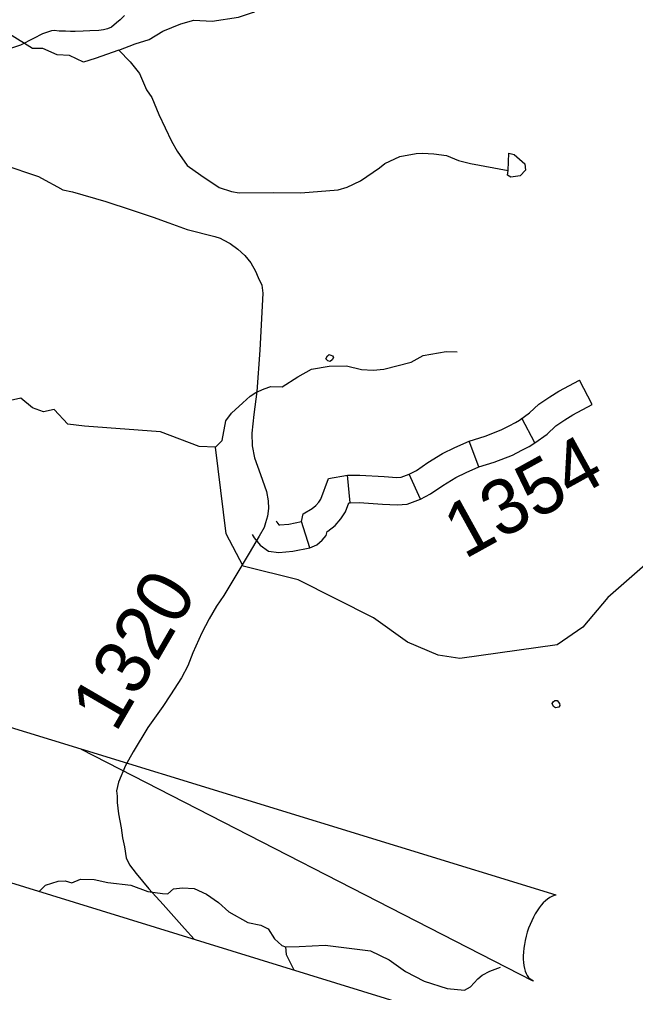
# Model space of a CAD drawing. Extents: x 1347947 to 1350662, y 1027710 to 1030532.
# Drawn here: x 1348191.6 to 1348242, y 1028722.6 to 1028802.3 of the extents above; entities that cross this region are included whole.
import ezdxf

# ---------------------------------------------------------------- set-up
doc = ezdxf.new("R2010")
doc.units = 0
for name, color, linetype in [('Default', 7, 'Continuous'), ('Prop Leader Line Light', 7, 'Continuous'), ('Prop North Arrow for Plan Sheets CELL', 7, 'Continuous'), ('Prop WCC CELL', 7, 'Continuous')]:
    doc.layers.add(name, color=color, linetype=linetype)

msp = doc.modelspace()

# ---------------------------------------------------------------- linework, layer by layer
at = {"layer": 'Default'}
for p, q in [((1348199.71, 1028799.768), (1348200.64, 1028798.811)), ((1348238.502, 1028770.744), (1348237.451, 1028772.733)), ((1348233.802, 1028767.597), (1348232.741, 1028769.606)), ((1348229.202, 1028765.617), (1348228.419, 1028767.73)), ((1348224.426, 1028762.973), (1348223.513, 1028765.035)), ((1348218.68, 1028762.687), (1348218.457, 1028764.932)), ((1348215.372, 1028759.001), (1348214.675, 1028761.153))]:
    msp.add_line(p, q, dxfattribs=at)
for points in [[(1348199.71, 1028799.768), (1348201.069, 1028800.27), (1348202.213, 1028800.625), (1348203.313, 1028801.32), (1348204.79, 1028801.926), (1348205.865, 1028802.202), (1348207.367, 1028802.124), (1348209.527, 1028802.47), (1348210.745, 1028802.859), (1348212.365, 1028803.82), (1348216.434, 1028804.782), (1348217.633, 1028805.178), (1348219.233, 1028805.496), (1348221.756, 1028806.061), (1348222.096, 1028805.983), (1348222.959, 1028806.7), (1348224.117, 1028807.212), (1348225.207, 1028807.3), (1348227.046, 1028807.308)], [(1348200.195, 1028802.591), (1348199.82, 1028802.247), (1348199.539, 1028801.998), (1348199.118, 1028801.646), (1348198.794, 1028801.507), (1348198.476, 1028801.412), (1348198.072, 1028801.364), (1348197.346, 1028801.352), (1348196.79, 1028801.3), (1348196.159, 1028801.273), (1348195.752, 1028801.298), (1348195.36, 1028801.318), (1348194.841, 1028801.304), (1348194.427, 1028801.356), (1348194.204, 1028801.332), (1348193.468, 1028801.087), (1348192.72, 1028800.725), (1348191.656, 1028800.159), (1348190.927, 1028799.907), (1348189.94, 1028799.78), (1348188.78, 1028799.71), (1348187.697, 1028799.672), (1348186.821, 1028799.833)], [(1348199.71, 1028799.768), (1348197.785, 1028799.07), (1348196.825, 1028798.777), (1348195.689, 1028799.329), (1348194.672, 1028799.377), (1348193.487, 1028799.904), (1348192.653, 1028799.892), (1348190.781, 1028801.069)], [(1348200.64, 1028798.811), (1348201.422, 1028797.841), (1348201.988, 1028796.496), (1348202.421, 1028795.87), (1348202.994, 1028794.482), (1348204.04, 1028792.295), (1348204.508, 1028791.479), (1348205.323, 1028790.315), (1348206.43, 1028789.517), (1348207.953, 1028788.512), (1348208.96, 1028788.179), (1348209.59, 1028788.059), (1348212.354, 1028788.088), (1348214.63, 1028788.062), (1348217.697, 1028788.311), (1348218.424, 1028788.526), (1348219.504, 1028789.043), (1348221.071, 1028790.129), (1348221.498, 1028790.471), (1348222.742, 1028791.053)], [(1348183.751, 1028792.494), (1348187.272, 1028791.256), (1348190.213, 1028790.399), (1348193.156, 1028789.399), (1348193.699, 1028789.106), (1348194.712, 1028788.569), (1348195.143, 1028788.322), (1348195.92, 1028788.154), (1348198.65, 1028787.357), (1348200.732, 1028786.675), (1348202.535, 1028786.072), (1348203.816, 1028785.622), (1348205.314, 1028785.076), (1348207.576, 1028784.481), (1348208.014, 1028784.346), (1348208.259, 1028784.233), (1348208.846, 1028783.917), (1348209.48, 1028783.453), (1348210.049, 1028782.928)], [(1348222.742, 1028791.053), (1348224.072, 1028791.3), (1348224.591, 1028791.323), (1348225.533, 1028791.278), (1348226.559, 1028791.122), (1348227.54, 1028790.719), (1348228.534, 1028790.473), (1348231.6, 1028789.908)], [(1348231.6, 1028789.908), (1348231.664, 1028791.315), (1348232.094, 1028791.205), (1348232.971, 1028790.448), (1348233.031, 1028789.918), (1348232.604, 1028789.456), (1348231.817, 1028789.364), (1348231.564, 1028789.514), (1348231.6, 1028789.908)], [(1348231.6, 1028789.908), (1348231.664, 1028791.315), (1348232.094, 1028791.205), (1348232.971, 1028790.448), (1348233.031, 1028789.918), (1348232.604, 1028789.456), (1348231.817, 1028789.364), (1348231.564, 1028789.514), (1348231.6, 1028789.908)], [(1348210.049, 1028782.928), (1348210.524, 1028782.344), (1348210.916, 1028781.667), (1348211.145, 1028781.145), (1348211.441, 1028780.501), (1348211.513, 1028779.855), (1348211.266, 1028775.173), (1348211.018, 1028771.81), (1348210.777, 1028769.923), (1348210.62, 1028768.397), (1348210.643, 1028767.344), (1348210.834, 1028766.378), (1348211.325, 1028765.007), (1348211.829, 1028763.598), (1348211.964, 1028762.84), (1348211.993, 1028762.217), (1348211.901, 1028761.575), (1348211.732, 1028761.033), (1348211.623, 1028760.645)], [(1348207.638, 1028767.241), (1348208.176, 1028767.787), (1348208.476, 1028769.395), (1348208.961, 1028770.02), (1348209.87, 1028770.863), (1348210.476, 1028771.426), (1348210.943, 1028771.71), (1348211.624, 1028772.022), (1348212.175, 1028772.196), (1348213.088, 1028772.182), (1348214.391, 1028772.988), (1348215.491, 1028773.621), (1348216.95, 1028773.884), (1348218.381, 1028773.891), (1348219.605, 1028773.603), (1348220.56, 1028773.533), (1348221.415, 1028773.64), (1348223.652, 1028774.201), (1348224.64, 1028774.75), (1348226.545, 1028775.061), (1348227.422, 1028775.058)], [(1348216.835, 1028774.312), (1348216.668, 1028774.473), (1348216.818, 1028774.725), (1348216.954, 1028774.822), (1348217.219, 1028774.707), (1348217.314, 1028774.572), (1348217.208, 1028774.385), (1348217.041, 1028774.259), (1348216.835, 1028774.312)], [(1348212.601, 1028761.201), (1348212.66, 1028761.098), (1348212.838, 1028760.882), (1348212.904, 1028760.873), (1348213.654, 1028760.937), (1348214.675, 1028761.153), (1348214.825, 1028761.778), (1348215.566, 1028762.222), (1348215.869, 1028762.46), (1348216.104, 1028762.736), (1348216.268, 1028762.981), (1348216.895, 1028764.659), (1348218.457, 1028764.932), (1348219.449, 1028764.957), (1348221.45, 1028764.825), (1348222.503, 1028764.76), (1348222.838, 1028764.789), (1348223.513, 1028765.035), (1348224.093, 1028765.339), (1348225.039, 1028765.972), (1348226.23, 1028766.723), (1348227.229, 1028767.218), (1348228.419, 1028767.73), (1348229.722, 1028768.139), (1348231.048, 1028768.655), (1348231.703, 1028768.981), (1348232.206, 1028769.251), (1348232.543, 1028769.463), (1348233.355, 1028770.051), (1348234.108, 1028770.762), (1348235.021, 1028771.353), (1348235.749, 1028771.835), (1348237.451, 1028772.733)], [(1348246.557, 1028760.877), (1348239.774, 1028754.932), (1348237.726, 1028752.503), (1348235.611, 1028751.037), (1348227.638, 1028749.93), (1348225.865, 1028750.214), (1348223.355, 1028751.262), (1348220.573, 1028753.261), (1348214.415, 1028756.381), (1348209.916, 1028757.493), (1348208.52, 1028760.13), (1348207.638, 1028767.241), (1348206.299, 1028767.295), (1348203.138, 1028768.487), (1348196.922, 1028768.972), (1348195.535, 1028769.12), (1348194.423, 1028770.322), (1348193.548, 1028770.122), (1348192.645, 1028770.456), (1348191.689, 1028771.253), (1348189.497, 1028770.751)], [(1348210.645, 1028760.089), (1348210.802, 1028759.813), (1348211.306, 1028759.205), (1348211.989, 1028758.732), (1348212.839, 1028758.609), (1348213.984, 1028758.707), (1348215.372, 1028759.001), (1348215.944, 1028759.235), (1348216.388, 1028759.607), (1348216.714, 1028760.006), (1348216.793, 1028760.333), (1348216.846, 1028760.365), (1348217.437, 1028760.831), (1348217.9, 1028761.374), (1348218.284, 1028761.946), (1348218.552, 1028762.665), (1348218.68, 1028762.687), (1348219.403, 1028762.705), (1348221.307, 1028762.58), (1348222.53, 1028762.504), (1348223.327, 1028762.573), (1348224.426, 1028762.973), (1348225.245, 1028763.403), (1348226.264, 1028764.085), (1348227.332, 1028764.759), (1348228.173, 1028765.175), (1348229.202, 1028765.617), (1348230.468, 1028766.015), (1348231.958, 1028766.595), (1348232.737, 1028766.982), (1348233.339, 1028767.306), (1348233.803, 1028767.598), (1348234.794, 1028768.315), (1348235.503, 1028768.986), (1348236.252, 1028769.47), (1348236.897, 1028769.897), (1348238.502, 1028770.744)], [(1348211.623, 1028760.645), (1348211.226, 1028759.961), (1348210.39, 1028758.566), (1348209.314, 1028756.731), (1348208.311, 1028755.086), (1348207.718, 1028754.208), (1348207.129, 1028753.189), (1348206.529, 1028752.032), (1348205.781, 1028750.379), (1348205.375, 1028749.329), (1348204.848, 1028748.348), (1348203.942, 1028746.942), (1348203.337, 1028745.991), (1348202.109, 1028744.279), (1348200.902, 1028742.275), (1348200.255, 1028741.167), (1348199.701, 1028739.81), (1348199.528, 1028739.083), (1348199.592, 1028738.65), (1348199.582, 1028738.127), (1348199.702, 1028737.204), (1348199.919, 1028736.063), (1348200.017, 1028735.243), (1348200.174, 1028734.497), (1348200.334, 1028733.608), (1348200.592, 1028733.031), (1348201.143, 1028732.304), (1348202.182, 1028731.062), (1348203.366, 1028729.78), (1348205.094, 1028727.824), (1348205.895, 1028726.936)], [(1348235.487, 1028745.883), (1348235.318, 1028745.984), (1348235.225, 1028746.241), (1348235.294, 1028746.38), (1348235.436, 1028746.493), (1348235.636, 1028746.483), (1348235.815, 1028746.238), (1348235.843, 1028746.085), (1348235.75, 1028745.935), (1348235.487, 1028745.883)], [(1348235.487, 1028745.883), (1348235.318, 1028745.984), (1348235.225, 1028746.241), (1348235.294, 1028746.38), (1348235.436, 1028746.493), (1348235.636, 1028746.483), (1348235.815, 1028746.238), (1348235.843, 1028746.085), (1348235.75, 1028745.935), (1348235.487, 1028745.883)], [(1348193.201, 1028730.845), (1348193.704, 1028731.374), (1348194.751, 1028731.681), (1348195.317, 1028731.726), (1348195.868, 1028731.552), (1348196.585, 1028731.852), (1348197.698, 1028731.828), (1348198.833, 1028731.571), (1348200.698, 1028731.364), (1348202.109, 1028730.849), (1348203.311, 1028730.671), (1348203.737, 1028730.664), (1348204.206, 1028731.07), (1348204.95, 1028731.155), (1348205.904, 1028731.085), (1348206.901, 1028730.612), (1348207.888, 1028729.939), (1348208.741, 1028729.17), (1348210.297, 1028728.317), (1348211.34, 1028728.093)], [(1348211.34, 1028728.093), (1348211.944, 1028727.78), (1348212.479, 1028726.978), (1348213.06, 1028726.428), (1348213.369, 1028726.319)], [(1348213.369, 1028726.319), (1348214.495, 1028726.331), (1348216.616, 1028726.443), (1348220.327, 1028725.975), (1348221.861, 1028725.232), (1348223.204, 1028724.29), (1348224.743, 1028723.504), (1348226.608, 1028722.89), (1348228.03, 1028722.756), (1348228.534, 1028723.029), (1348229.118, 1028723.702), (1348229.481, 1028723.982), (1348230.107, 1028724.312), (1348230.995, 1028724.633)], [(1348213.369, 1028726.319), (1348213.414, 1028725.692), (1348214.004, 1028724.526), (1348214.047, 1028724.425)]]:
    msp.add_lwpolyline(points, dxfattribs=at)
at = {"layer": 'Prop North Arrow for Plan Sheets CELL'}
for p, q in [((1348196.641, 1028742.493), (1348174.983, 1028749.163)), ((1348196.641, 1028742.493), (1348233.575, 1028723.561)), ((1348235.549, 1028730.556), (1348196.641, 1028742.493))]:
    msp.add_line(p, q, dxfattribs=at)
msp.add_ellipse((1348234.791, 1028727.022), major_axis=(1.102, 3.489), ratio=0.461098, start_param=0.201328, end_param=3.141593, dxfattribs=at)
at = {"layer": 'Prop WCC CELL'}
msp.add_line((1348067.182, 1028769.652), (1348285.23, 1028702.505), dxfattribs=at)

# ---------------------------------------------------------------- texts
at = {"layer": 'Prop Leader Line Light'}
for s, rotation, p in [('1354', 28.91335, (1348228.026, 1028758.018)), ('1320', 59.79854, (1348199.464, 1028743.765))]:
    msp.add_text(s, height=4.5, rotation=rotation, dxfattribs=at).set_placement(p)

doc.saveas('drawing.dxf')
